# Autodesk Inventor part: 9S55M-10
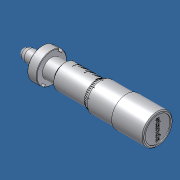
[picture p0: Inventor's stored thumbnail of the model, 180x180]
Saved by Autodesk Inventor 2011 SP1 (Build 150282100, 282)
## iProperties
Created: 2012-02
Part Number: 9S55M-10
Document SubType Name: Modeling
Designer: Darius
Density: 1 g/cm^3
Author: Darius
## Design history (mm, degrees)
feature "Base1"
body "Solid1"
